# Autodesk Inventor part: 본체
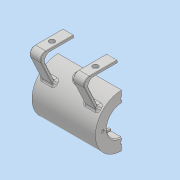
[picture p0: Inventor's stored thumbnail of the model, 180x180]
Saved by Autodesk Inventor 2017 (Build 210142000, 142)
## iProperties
Part Number: 본체
Material: 일반
Document SubType Name: Modeling
Designer: Administrator
Density: 1 g/cm^3
Appearance: 기본값
Author: Administrator
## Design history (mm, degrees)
sketch "스케치3"
  geometry: L1 (0, 29)-(35, 29); L2 (35, 29)-(35, 16); L3 (35, 16)-(23, 16); L4 (23, 16)-(23, 14); L5 (23, 14)-(21, 14); L6 (21, 14)-(21, 21); L7 (21, 21)-(0, 21); L8 (0, 21)-(0, 29); L9 (-7, 0)-(42, 0) reference; 1 further point
  constraints: 16 end point, 5 perpendicular, 1 horizontal, 1 parallel, 1 vertical, 1 vertical alignment
  dimensions: "d19" = 35 distance between parallel lines of L2 L8; "d20" = 12 distance of L2.end L3.end; "d21" = 2 distance of L4.end L5.end; "d22" = 16 distance from line of point (0, 0) L3; "d23" = 14 distance from line of point (0, 0) L5; "d24" = 21 distance from line of point (0, 0) L7; "d25" = 29 distance from line of point (0, 0) L1
revolve "회전1" sketch "스케치3" stored, may be unused: angle "d26" = 90 deg
sketch "스케치4" dims "d27" = 42
  geometry: 3 further points
  constraints: 2 vertical alignment, 1 coincident, 2 other
hole "구멍1" sketch "스케치4" at (0, 21) diameter "d28" = 3.242; stored, may be unused: countersink angle "d32" = 90 deg, drill point angle "d34" = 118 deg; dims "d29" = 8, "d30" = 4, "d31" = 2, "d33" = 10
node "작업 평면1"
sketch "스케치5"
  geometry: C1 r 5 at (0, 0); 1 further point
  constraints: 1 centre point, 1 coincident
  dimensions: "d39" = 10 diameter of C1
extrude "돌출1" join sketch "스케치5" stored distance "d40" = 10; taper "d41" = 0 deg
sketch "스케치6"
  geometry: 2 further points
  constraints: 1 coincident
hole "구멍2" sketch "스케치6" at (0, 0) diameter "d42" = 5.188; stored, may be unused: countersink angle "d46" = 90 deg, drill point angle "d48" = 118 deg; dims "d43" = 6, "d44" = 4, "d45" = 2, "d47" = 8
sketch "스케치7"
  geometry: C1 r 1.5 at (0, 0); 1 further point
  constraints: 1 centre point, 1 coincident
  dimensions: "d49" = 3 diameter of C1
extrude "돌출2" cut sketch "스케치7" distance "d50" = 24.75; taper "d51" = 0 deg
node "작업 평면2"
node "작업 평면3"
sketch "스케치9"
  geometry: L1 (55, 40.6)-(55, -40.6) reference; L2 (55, -40)-(55, 40); L3 (17.993, 22.743)-(55, 40); L4 (17.993, -22.743)-(55, -40); L5 (20.438, -20.574)-(52, -35.291); L6 (52, -35.291)-(52, 35.291); L7 (52, 35.291)-(20.438, 20.574); C1 r 1.621 at (-21, 0) reference; C2 r 1.621 at (0, -21) reference; C3 r 1.621 at (21, 0) reference; C4 r 1.621 at (0, 21) reference; C5 r 16 at (0, 0) reference; A1 r 29 centre (0, 0) between (17.993, 22.743) and (17.993, -22.743) reference; A2 r 29 centre (0, 0) between (17.993, 22.743) and (17.993, -22.743) reference; 1 further point
  constraints: 12 end point, 6 point on circle, 2 parallel, 2 point on line
  dimensions: "d54" = 80 distance of L2.end L2.start; "d55" = 40 vertical distance of C3.centre L2.start; "d56" = 65 deg angle of L1 L4; "d57" = 65 deg angle of L1 L3; "d59" = 3 distance between parallel lines of L4 L5; "d62" = 3 distance between parallel lines of L1 L6; "d63" = 3 distance between parallel lines of L3 L7
extrude "돌출3" join sketch "스케치9" distance "d64" = 12; taper "d65" = 0 deg
sketch "스케치10"
  geometry: L1 (0, 0)-(0, 29); L2 (0, 0)-(-10.945, 30.07); 1 further point
  constraints: 4 end point, 1 vertical, 1 vertical alignment, 1 other
  dimensions: "d68" = 20 deg angle of L2 L1; "d69" = 32 distance of L2.end point (0, 0)
node "작업 평면5"
sketch "스케치11"
  geometry: C1 r 6 at (0, 0); 1 further point
  constraints: 1 centre point, 1 coincident
  dimensions: "d70" = 12 diameter of C1
extrude "돌출4" join sketch "스케치11" stored distance "d71" = 12; taper "d72" = 0 deg
sketch "스케치12"
  geometry: 2 further points
  constraints: 1 coincident
hole "구멍3" sketch "스케치12" at (0, 0) diameter "d73" = 5.188; stored, may be unused: countersink angle "d77" = 90 deg, drill point angle "d79" = 118 deg; dims "d74" = 20, "d75" = 4, "d76" = 2, "d78" = 20.5
sketch "스케치13"
  geometry: L1 (0, 0)-(0, 80) reference; L2 (0, 0)-(12, 0) reference; C1 r 3 at (6, 58); 1 further point
  constraints: 1 centre point
  dimensions: "d80" = 6 diameter of C1; "d81" = 6 distance from line of C1.centre L1; "d82" = 18 vertical distance of point (30, 40) C1.centre
extrude "돌출5" cut sketch "스케치13" distance "d83" = 11.75; taper "d84" = 0 deg
fillet "모깎기1" dims "d91" = 6
fillet "모깎기2" dims "d92" = 0.5
fillet "모깎기3" dims "d93" = 3
fillet "모깎기4" dims "d94" = 0.3
fillet "모깎기5" dims "d95" = 1
fillet "모깎기6" dims "d96" = 1
node "작업 평면6"
sketch "스케치14"
  geometry: L1 (35, 29)-(35, -29) reference; L2 (35, -29)-(-35, -29) reference; 2 further points
  constraints: 1 other
  dimensions: "d98" = 35 distance from line of point (0, 0) L1; "d99" = 29 distance from line of point (0, 0) L2
feature "엠보싱1" sketch "스케치14" dims "d19" = 35, "d20" = 12, "d21" = 2, "d22" = 16, "d23" = 14, "d24" = 21, "d25" = 29, "d100" = 0.5, "d101" = 0
chamfer "모따기1" distance "d102" = 1; stored, may be unused: second distance "d103" = 2, angle "d104" = 45 deg
fillet "모깎기7" dims "d105" = 3
node "솔리드1"
pattern_circular "원형 패턴1" dims angle "d36" = 360 deg
mirror "미러1"
mirror "미러2"
pattern_linear "직사각형 패턴1" dims "d87" = 36, "d90" = 48
node "투영된 루프1"
other parameters: "d38" = -32, "d52" = 55, "d53" = -5, "d97" = 29
